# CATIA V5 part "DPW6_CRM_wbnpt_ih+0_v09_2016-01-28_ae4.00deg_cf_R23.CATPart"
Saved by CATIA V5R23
Part number: DPW6_CRM_wbnpt_ih+0_v09_2016-01-28_ae4
Bounding box of the stored display mesh (mm): x 2349.5 to 66711.883, y -0.001 to 29447.289, z -62.194 to 8715.782
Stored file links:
  C:\Users\mrg\work\AIAA_DPW\DPW6\DLR_meshes\all\4deg00\DPW6_CRM_wbnpt_ih+0_v09_2016-01-28_ae4.00deg_cf.CATPart

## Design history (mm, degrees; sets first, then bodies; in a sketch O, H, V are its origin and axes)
MechanicalRefPlane1 "xy-plane"
MechanicalRefPlane2 "yz-plane"
MechanicalRefPlane3 "zx-plane"
Set1
  DatumSurface1 to DatumSurface3
Body1 (main body)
